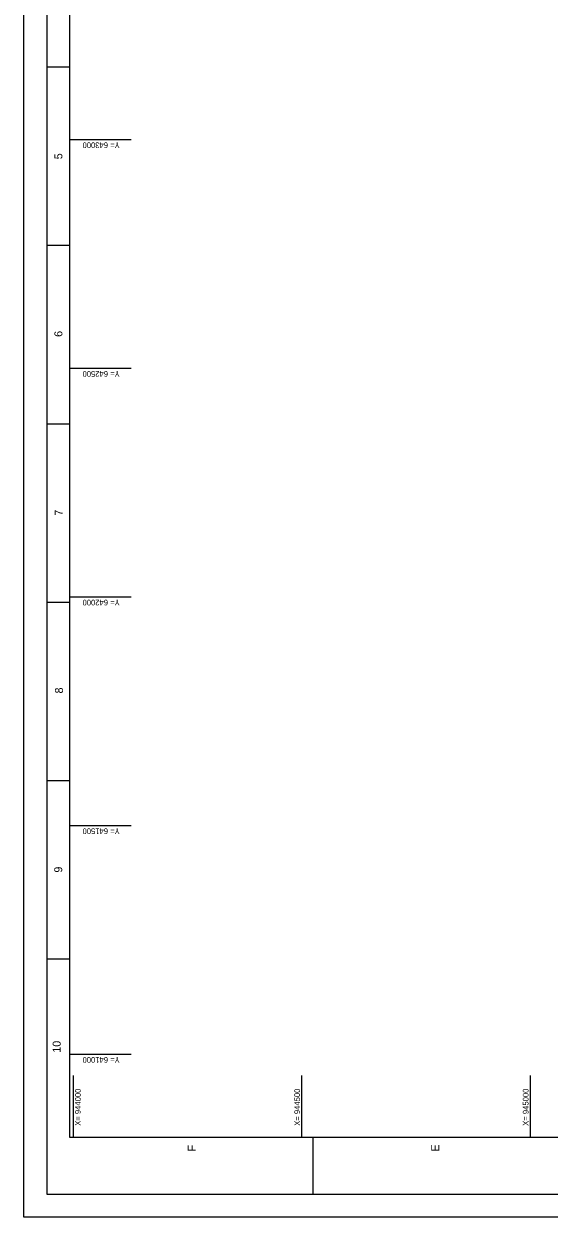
# Model space of a CAD drawing. Extents: x 943892 to 947291, y 640645 to 645045.
# Drawn here: x 943892 to 945041, y 640645 to 643254 of the extents above; entities that cross this region are included whole.
import ezdxf

# ---------------------------------------------------------------- set-up
doc = ezdxf.new("R2010")
doc.units = 0
for name, color, linetype in [('G-ANNO-NPLT', 7, 'Continuous'), ('G-ANNO-TTLB', 7, 'Continuous'), ('V-TOPO-COOR-STAT', 7, 'Continuous')]:
    doc.layers.add(name, color=color, linetype=linetype)

msp = doc.modelspace()

# ---------------------------------------------------------------- linework, layer by layer
at = {"layer": 'G-ANNO-NPLT'}
msp.add_lwpolyline([(943891.5, 640644.6), (943891.5, 645044.6), (947291.5, 645044.6), (947291.5, 640644.6)], close=True, dxfattribs=at)
msp.add_lwpolyline([(943941.5, 640644.6), (943891.5, 640644.6), (943891.5, 640694.6)], dxfattribs=at)
at = {"layer": 'G-ANNO-TTLB'}
for p, q in [((943941.5, 643159.6), (943991.5, 643159.6)), ((943941.5, 642769.6), (943991.5, 642769.6)), ((943941.5, 642379.6), (943991.5, 642379.6)), ((943941.5, 641989.6), (943991.5, 641989.6)), ((943941.5, 641599.6), (943991.5, 641599.6)), ((943941.5, 641599.6), (943991.5, 641599.6)), ((943941.5, 641209.6), (943991.5, 641209.6)), ((944525, 640694.6), (944525, 640819.6))]:
    msp.add_line(p, q, dxfattribs=at)
for points in [[(947241.5, 640694.6), (947241.5, 644994.6), (943941.5, 644994.6), (943941.5, 640694.6)], [(943991.5, 644944.6), (943991.5, 640819.6), (947191.5, 640819.6), (947191.5, 644944.6)]]:
    msp.add_lwpolyline(points, close=True, dxfattribs=at)
at = {"layer": 'V-TOPO-COOR-STAT'}
for p, q in [((944126.5, 643000), (943991.5, 643000)), ((944126.5, 642500), (943991.5, 642500)), ((944126.5, 642000), (943991.5, 642000)), ((944126.5, 641500), (943991.5, 641500)), ((944126.5, 641000), (943991.5, 641000)), ((944000, 640819.6), (944000, 640954.6)), ((944500, 640819.6), (944500, 640954.6)), ((945000, 640819.6), (945000, 640954.6))]:
    msp.add_line(p, q, dxfattribs=at)

# ---------------------------------------------------------------- texts
at = {"layer": 'G-ANNO-TTLB'}
for s, p in [('5', (943975.8, 642957.8)), ('6', (943975.8, 642569.4)), ('7', (943976.5, 642178.4)), ('8', (943977.2, 641789.7)), ('9', (943975.6, 641398)), ('10', (943972.1, 641004.2)), ('F', (944267.9, 640788.2)), ('E', (944800.6, 640788))]:
    msp.add_text(s, height=17.5, rotation=90, dxfattribs=at).set_placement(p)
at = {"layer": 'V-TOPO-COOR-STAT'}
for s, rotation, p in [('Y= 643000', 180, (944101.3, 642994.7)), ('Y= 642500', 180, (944101.3, 642494.7)), ('Y= 642000', 180, (944101.3, 641994.7)), ('Y= 641500', 180, (944101.3, 641494.7)), ('Y= 641000', 180, (944101.3, 640994.7)), ('X= 944000', 90, (944016, 640844.3)), ('X= 944500', 90, (944496, 640844.3)), ('X= 945000', 90, (944996, 640844.3))]:
    msp.add_text(s, height=12.5, rotation=rotation, dxfattribs=at).set_placement(p)

doc.saveas('drawing.dxf')
